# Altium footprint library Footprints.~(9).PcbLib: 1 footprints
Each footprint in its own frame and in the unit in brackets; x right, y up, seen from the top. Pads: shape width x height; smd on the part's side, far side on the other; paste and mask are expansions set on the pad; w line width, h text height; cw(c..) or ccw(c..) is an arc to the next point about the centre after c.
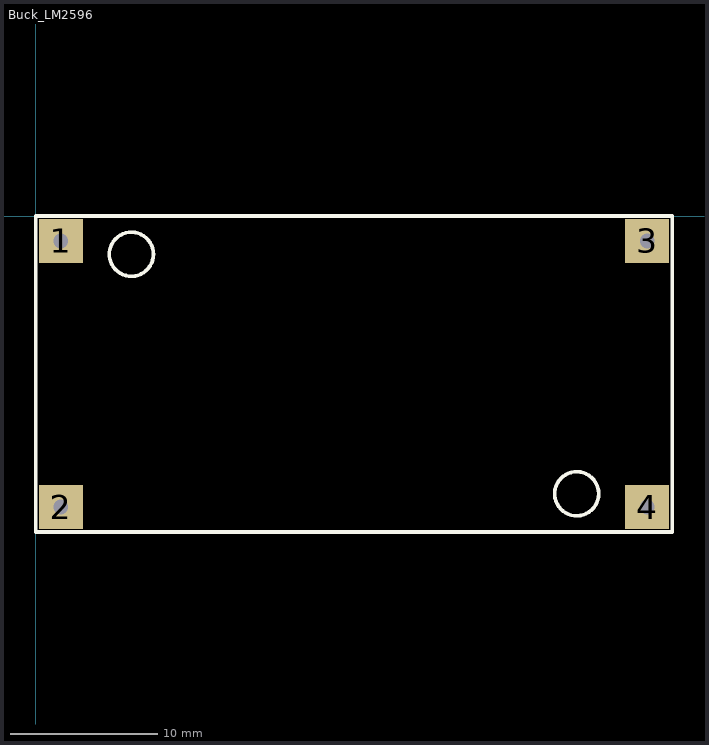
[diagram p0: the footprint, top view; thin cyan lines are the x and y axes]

## Buck_LM2596 [mm]
height 11.5
pads (4):
  rect 3x3 hole 1: 1(1.7,-1.7) 2(1.7,-19.8) 3(41.6,-1.7) 4(41.6,-19.8)
Top Overlay:
  circle w0.254: c6.5,-2.6 r1.5
  circle w0.254: c36.8,-18.9 r1.5
  lines w0.254: 0,-21.5 43.3,-21.5 43.3,0 0,0 0,-21.5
